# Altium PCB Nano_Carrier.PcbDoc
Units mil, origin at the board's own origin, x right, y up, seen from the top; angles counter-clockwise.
Board outline 1968.5 x 3149.61 mil, 4 copper layers (Top, PWR, MID, Bottom), stack 63.464 mil thick; 2 components, 29 nets, 34 pads, 0 vias.
Unrouted connection lines stored in the file: 1.
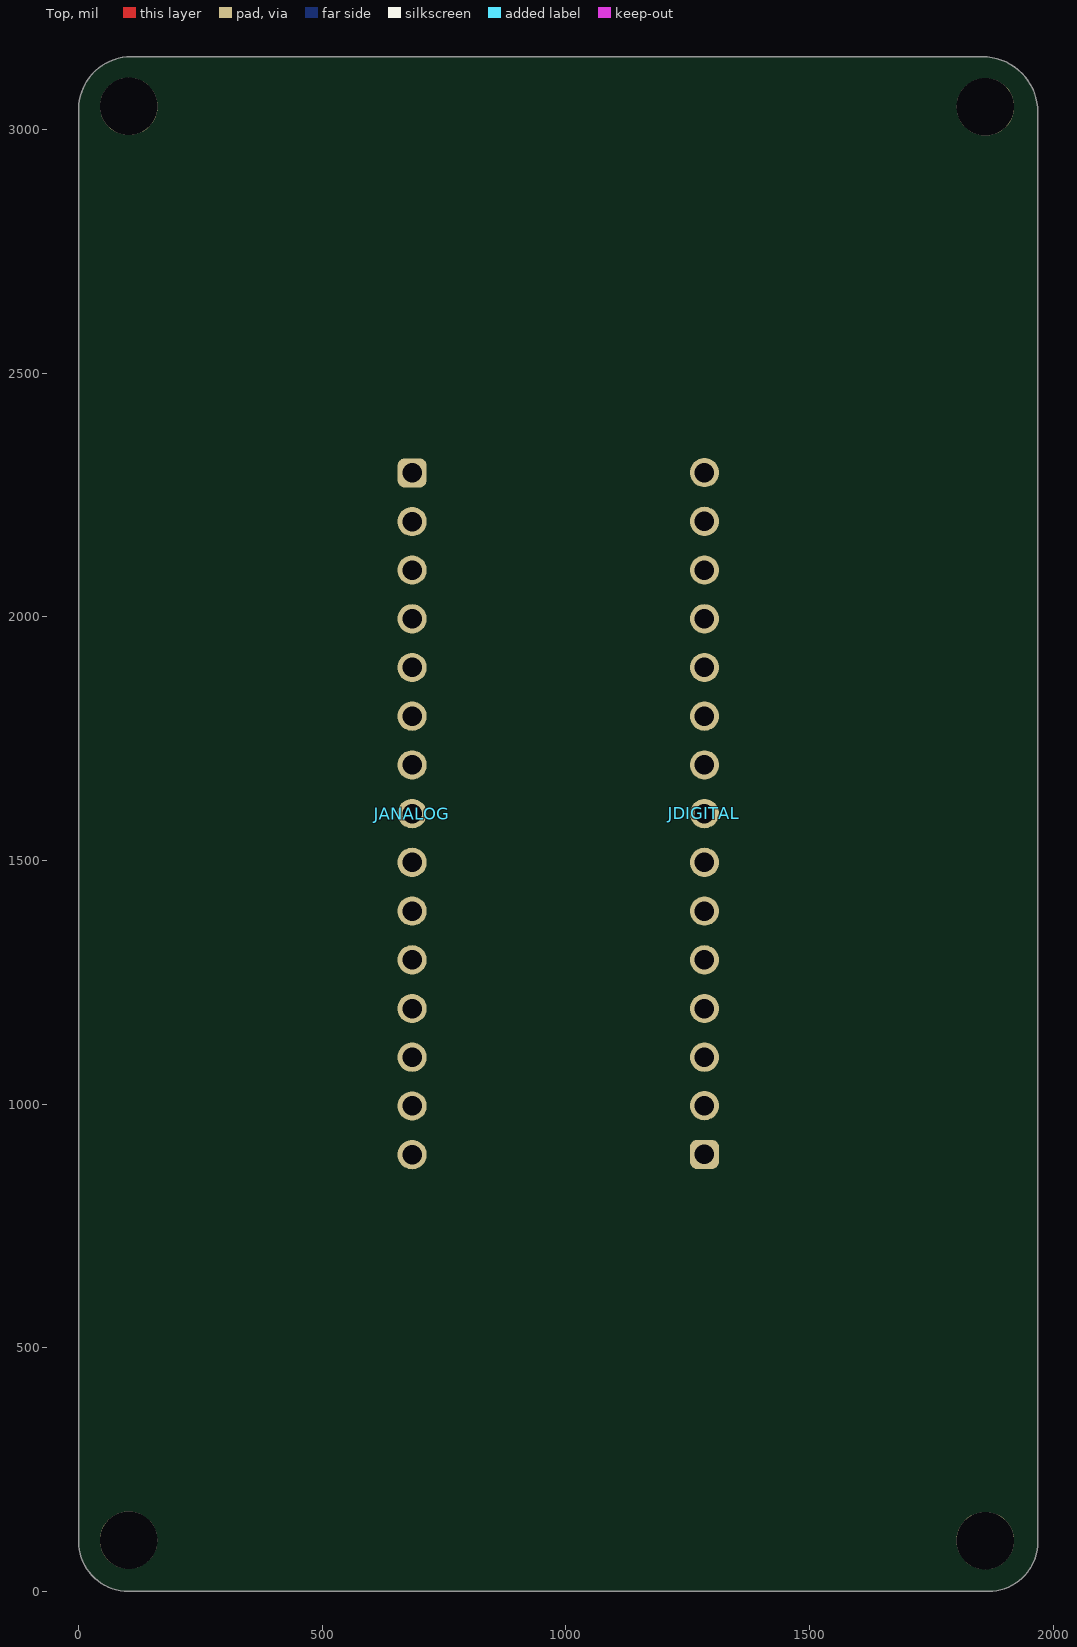
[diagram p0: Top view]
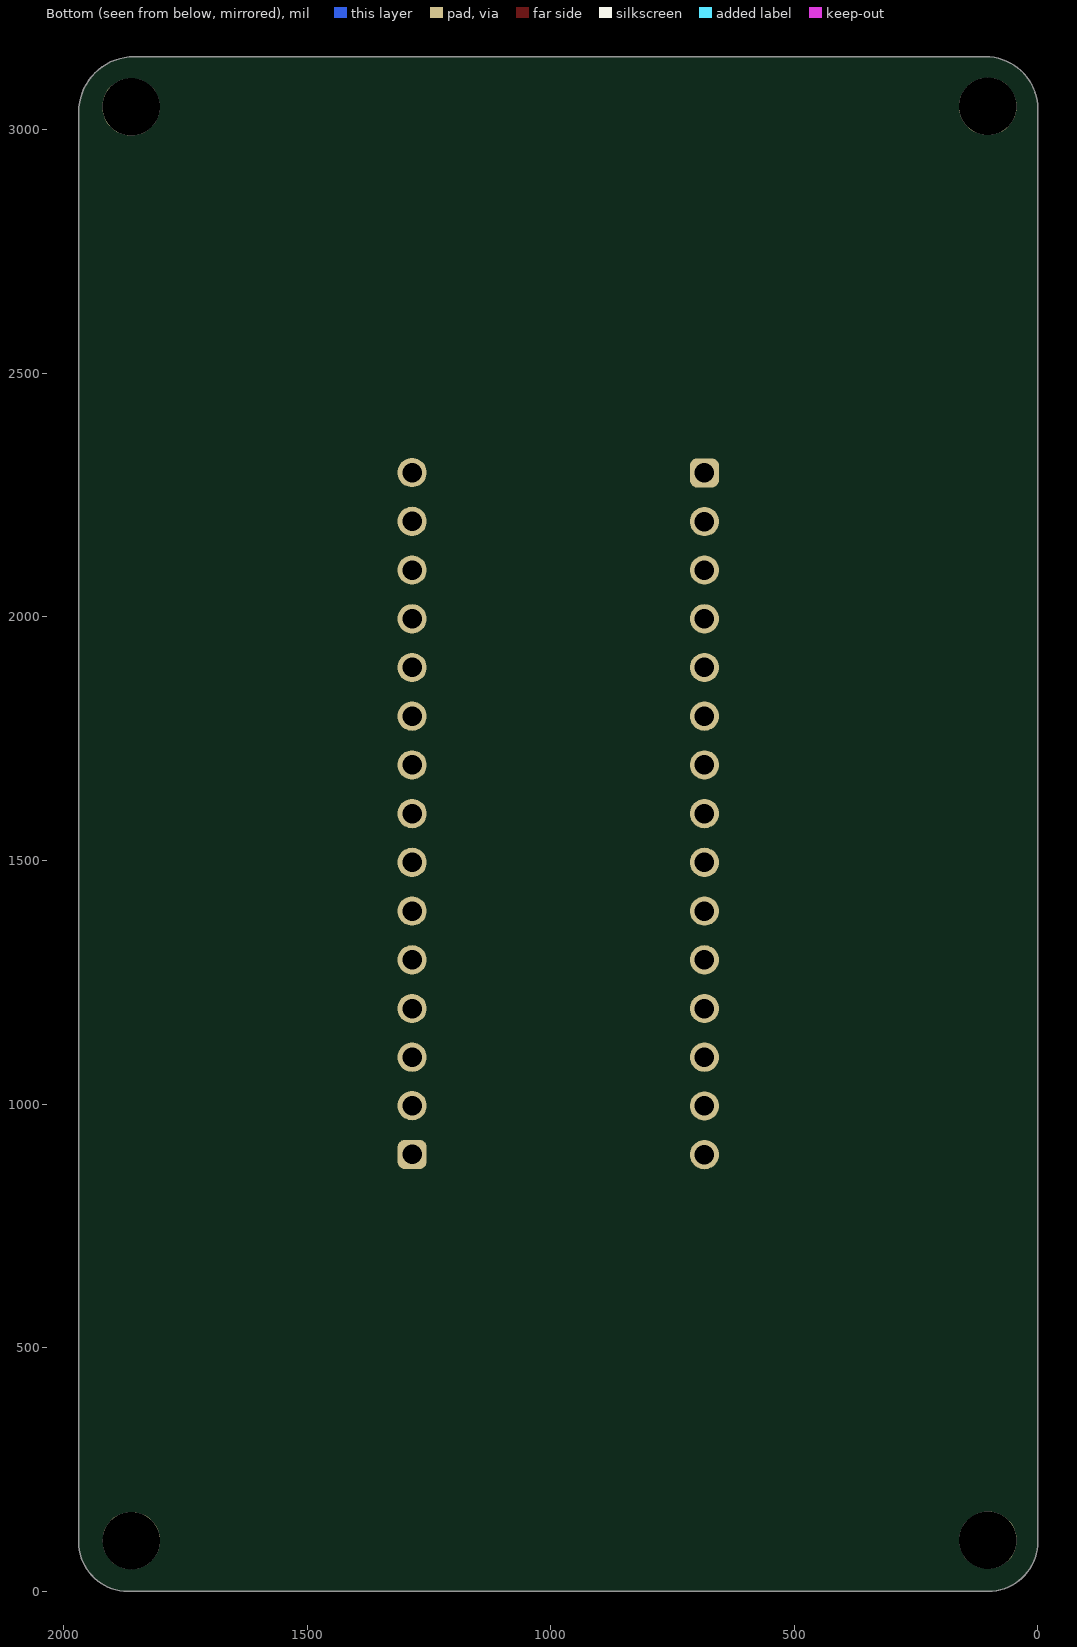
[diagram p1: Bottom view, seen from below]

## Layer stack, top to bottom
Top Solder: solder mask 0.3937, Solder Resist, Dk 3.5
Top: signal copper 1.3778
Dielectric 1: core 14.0157, FR-4, Dk 4.8
PWR: signal copper 1.3778
Dielectric3: core 29.9213, FR-4, Dk 4.8
MID: signal copper 1.3778
Dielectric2: dielectric 14.0157, FR-4, Dk 4.8
Bottom: signal copper 1.3778
Bottom Solder: solder mask 0.4, Solder Resist, Dk 3.5

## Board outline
1867.6,0 101.68,0 cw(c101.68,101.68) 0,101.68 0,3042.33 cw(c107.27,3042.34) 107.27,3149.61 1855.2,3149.61 cw(c1855.19,3036.31) 1968.5,3036.31 1968.5,101.33 cw(c1867.6,100.9)

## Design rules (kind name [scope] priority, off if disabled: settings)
Clearance "Clearance (Same Net)" [All] p1: gap=7 ignorepadtopadclearanceinfootprint=FALSE except(6: SMDPad-SMDPad SMDPad-THPad SMDPad-Via)
Clearance [All] p2: gap=7 ignorepadtopadclearanceinfootprint=FALSE
HoleSize [All] p1: absolutevalues=TRUE maxlimit=100000 minlimit=11.81 maxpercent=80.000 minpercent=20.000
HoleToHoleClearance mdDrill [All] p1: gap=10 allowstackedmicrovias=TRUE
PasteMaskExpansion Expansion_SMDPaste_OFF [InPadClass('SMDPaste_OFF')] p1: expansion=0
PasteMaskExpansion mlMinCreamFrame [All] p2: expansion=0
PolygonConnect PolygonConnect_For_PolygonThermal_ON_Width120000_Gap100000 [InPolygonClass('PolygonThermal_ON_Width120000_Gap100000')] p1: connectstyle=Relief reliefconductorwidth=12 reliefentries=4 polygonreliefangle="90 Angle" airgapwidth=10
PolygonConnect PolygonConnect_For_PolygonThermal_OFF [InPolygonClass('PolygonThermal_OFF')] p2: connectstyle=Direct reliefconductorwidth=10 reliefentries=4 polygonreliefangle="90 Angle" airgapwidth=10
PolygonConnect PolygonConnect_For_PolygonThermal_ON_Width160000_Gap100000 [InPolygonClass('PolygonThermal_ON_Width160000_Gap100000')] p3: connectstyle=Relief reliefconductorwidth=16 reliefentries=4 polygonreliefangle="90 Angle" airgapwidth=10
PolygonConnect ThermalVias [IsVia] p4: connectstyle=Direct reliefconductorwidth=10 reliefentries=4 polygonreliefangle="90 Angle" airgapwidth=10
PolygonConnect [All] p5: connectstyle=Relief reliefconductorwidth=10 reliefentries=4 polygonreliefangle="90 Angle" airgapwidth=10
RoomDefinition NANO-1 [InComponentClass('NANO-1')] p1: confinementstyle=ConfineIn formatcopy=TRUE lockcomponents=FALSE outline 476.38,476.38 1488.19,476.38 1488.19,3165.35 476.38,3165.35
RoutingVias [All] p1: holewidth=11.81 width=27.81 viastyle="Through Hole" minholewidth=11.81 minwidth=27.81 maxholewidth=100 maxwidth=100
SolderMaskExpansion Expansion_SMDSolder_OFF [InPadClass('SMDSolder_OFF')] p1: expansion=0 istentingtop=FALSE
SolderMaskExpansion mlMinStopFrame [All] p2: expansion=3.94 istentingtop=FALSE
Width [All] p1: maxlimit=10000 minlimit=11.81 preferedwidth=11.81
27 further rules are at their usual default settings.

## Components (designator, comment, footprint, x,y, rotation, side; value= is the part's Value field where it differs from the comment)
JANALOG "PINHD-SOCKET-JANALOG-NANO" "New footprint 1"#1 684.25,1596.06 r270 top
JDIGITAL "PINHD-SOCKET-JDIGITAL-NANO" "New footprint 1"#2 1284.25,1596.06 r270 top

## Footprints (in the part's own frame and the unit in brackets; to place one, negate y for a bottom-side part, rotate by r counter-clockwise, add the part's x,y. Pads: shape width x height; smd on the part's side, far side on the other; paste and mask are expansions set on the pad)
"New footprint 1"#1 [mil]
  rrect50% 60x60 hole 40 paste-100: 1(-699.41,0)
  round 60 hole 40 paste-100: 2(-599.41,0) 3(-500,0) 4(-400,0) 5(-300,0) 6(-200,0) 7(-100,0) 8(0,0) 9(100,0) 10(200,0) 11(300,0) 12(400,0) 13(500,0) 14(600,0) 15(700,0)
  body extent -760,-50 755,50, height 335
"New footprint 1"#2 [mil]
  rrect50% 60x60 hole 40 paste-100: 1(699.41,0)
  round 60 hole 40 paste-100: 2(599.41,0) 3(500,0) 4(400,0) 5(300,0) 6(200,0) 7(100,0) 8(0,0) 9(-100,0) 10(-200,0) 11(-300,0) 12(-400,0) 13(-500,0) 14(-600,0) 15(-700,0)
  body extent -755,-50 760,50, height 335

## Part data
JANALOG: library part CMP-003-0042-A.1, "CONN THD SOCKET F/1/D 15V JANALOG NANO-TYPE"
JDIGITAL: library part CMP-003-0044-A.1, "CONN THD SOCKET F/1/D 15V JDIGITAL NANO-TYPE"

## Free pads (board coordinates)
  round 118.11 hole 118.11 unplated: MH1(102.36,104.72) MH2(1860.63,103.94) MH3(1861.02,3046.85) MH4(102.76,3047.64)

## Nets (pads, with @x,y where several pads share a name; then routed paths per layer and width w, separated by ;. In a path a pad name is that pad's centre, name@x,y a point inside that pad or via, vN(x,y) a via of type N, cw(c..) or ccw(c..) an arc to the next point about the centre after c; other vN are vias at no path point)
+3.3V: JANALOG.2
+VM2: JANALOG.15
A0: JANALOG.4
A1: JANALOG.5
A2: JANALOG.6
A3: JANALOG.7
A4: JANALOG.8
A5: JANALOG.9
A6: JANALOG.10
A7: JANALOG.11
AREF: JANALOG.3
D2: JDIGITAL.5
D3: JDIGITAL.6
D4: JDIGITAL.7
D5: JDIGITAL.8
D6: JDIGITAL.9
D7: JDIGITAL.10
D8: JDIGITAL.11
D9: JDIGITAL.12
D10: JDIGITAL.13
GND: JANALOG.14 JDIGITAL.4
MISO: JDIGITAL.15
MOSI: JDIGITAL.14
RST_NANO1: JDIGITAL.3
RST_NANO2: JANALOG.13
RX: JDIGITAL.2
SCK: JANALOG.1
TX: JDIGITAL.1
VBUS: JANALOG.12

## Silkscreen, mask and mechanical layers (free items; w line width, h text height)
Board (Mech4):
  the board outline again, w5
